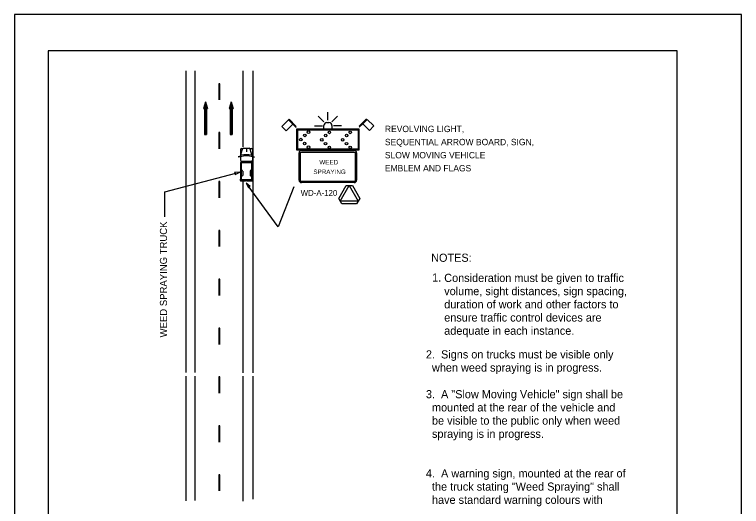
# Model space of a CAD drawing. Extents: x 1570 to 1794, y 169 to 448.
# Drawn here: x 1578.5 to 1794.5, y 301.9 to 448 of the extents above; entities that cross this region are included whole.
import ezdxf

# ---------------------------------------------------------------- set-up
doc = ezdxf.new("R2010")
doc.units = 0
for name, color, linetype in [('Level 1', 7, 'Continuous'), ('Level 10', 7, 'Continuous'), ('Level 2', 7, 'Continuous'), ('Level 44', 7, 'Continuous'), ('Level 60', 7, 'Continuous')]:
    doc.layers.add(name, color=color, linetype=linetype)

msp = doc.modelspace()

# ---------------------------------------------------------------- linework, layer by layer
at = {"layer": 'Level 1'}
for p, q in [((1646.51, 408.35), (1648.24, 408.35)), ((1647.37, 408.35), (1647.37, 407.24)), ((1645.6, 407.91), (1645.6, 404.82)), ((1645.66, 406.03), (1646.21, 408.09)), ((1645.9, 408.22), (1646.26, 408.22)), ((1648.49, 408.22), (1648.85, 408.22)), ((1649.07, 406.03), (1648.53, 408.09)), ((1649.14, 407.91), (1649.14, 404.82)), ((1645.6, 405.81), (1644.96, 405.74)), ((1645.6, 405.8), (1644.96, 405.72)), ((1645.6, 405.78), (1644.96, 405.7)), ((1645.6, 405.8), (1645.66, 406.03)), ((1645.6, 405.41), (1645.6, 405.41)), ((1645.6, 403.97), (1645.6, 399.15)), ((1645.82, 403.97), (1645.82, 399.15)), ((1645.9, 404.52), (1648.85, 404.52)), ((1645.9, 404.27), (1648.85, 404.27)), ((1645.9, 404.05), (1648.85, 404.05)), ((1648.92, 403.97), (1648.92, 399.15)), ((1649.14, 405.8), (1649.08, 406.03)), ((1649.14, 405.81), (1649.79, 405.74)), ((1649.14, 405.8), (1649.79, 405.72)), ((1649.14, 405.78), (1649.79, 405.7)), ((1649.14, 403.97), (1649.14, 399.15)), ((1645.82, 401.76), (1646.02, 401.76)), ((1648.92, 401.76), (1648.72, 401.76)), ((1645.82, 400.02), (1646.02, 400.02)), ((1646.26, 401.53), (1646.26, 400.25)), ((1648.49, 401.53), (1648.49, 400.25)), ((1648.92, 400.02), (1648.72, 400.02)), ((1645.54, 399.15), (1645.54, 398.89)), ((1645.83, 398.6), (1647.15, 398.6)), ((1645.9, 399.08), (1648.85, 399.08)), ((1645.9, 398.86), (1648.85, 398.86)), ((1647.6, 398.6), (1648.92, 398.6)), ((1649.21, 399.15), (1649.21, 398.89)), ((1674.8, 393.42), (1677, 397.23)), ((1675.26, 392.62), (1677.92, 397.23)), ((1677, 397.23), (1678.85, 397.23)), ((1677.92, 397.23), (1680.59, 392.62)), ((1678.85, 397.23), (1681.05, 393.42)), ((1675.72, 391.82), (1674.8, 393.42)), ((1681.05, 393.42), (1680.13, 391.82)), ((1680.59, 392.62), (1675.26, 392.62)), ((1680.13, 391.82), (1675.72, 391.82))]:
    msp.add_line(p, q, dxfattribs=at)
for centre, radius, start, end in [((1646.51, 408.05), 0.297, 90, 172.554), ((1648.24, 408.05), 0.297, 7.446, 90), ((1645.9, 407.92), 0.297, 90, 180), ((1645.95, 405.96), 0.297, 101.1133, 164.8989), ((1647.37, 398.73), 7.66, 78.8894, 101.1106), ((1648.85, 407.92), 0.297, 0, 90), ((1648.79, 405.96), 0.297, 14.8586, 78.8916), ((1647.37, 398.73), 7.29, 75.9432, 104.0544), ((1645.9, 404.82), 0.297, 180, 270), ((1645.9, 403.97), 0.297, 90, 180), ((1645.9, 403.97), 0.0766, 90, 180), ((1648.85, 404.82), 0.297, 270, 360), ((1648.85, 403.97), 0.297, 360, 90), ((1648.85, 403.97), 0.0766, 360, 90), ((1645.9, 399.15), 0.297, 180, 270), ((1645.9, 399.15), 0.0766, 180, 270), ((1648.85, 399.15), 0.297, 270, 360), ((1648.85, 399.15), 0.0766, 270, 360)]:
    msp.add_arc(centre, radius, start, end, dxfattribs=at)
at = {"layer": 'Level 10'}
for p, q in [((1786.24, 448.02), (1786.24, 448.02)), ((1629.33, 431.35), (1629.33, 341.73)), ((1632.06, 431.35), (1632.06, 341.68)), ((1646.28, 431.35), (1646.28, 408.73)), ((1649.3, 431.35), (1649.3, 341.62)), ((1635.19, 422.06), (1634.61, 420.13)), ((1634.97, 421.34), (1634.97, 412.39)), ((1635.05, 421.58), (1635.05, 412.39)), ((1635.12, 421.82), (1635.12, 412.39)), ((1635.19, 422.06), (1635.19, 412.39)), ((1635.19, 422.06), (1635.77, 420.13)), ((1635.26, 421.82), (1635.26, 412.39)), ((1635.34, 421.58), (1635.34, 412.39)), ((1635.41, 421.34), (1635.41, 412.39)), ((1642.84, 422.06), (1642.26, 420.13)), ((1642.62, 421.34), (1642.62, 412.39)), ((1642.7, 421.58), (1642.7, 412.39)), ((1642.77, 421.82), (1642.77, 412.39)), ((1642.84, 422.06), (1642.84, 412.39)), ((1642.84, 422.06), (1643.42, 420.13)), ((1642.91, 421.82), (1642.91, 412.39)), ((1642.99, 421.58), (1642.99, 412.39)), ((1643.06, 421.34), (1643.06, 412.39)), ((1634.61, 420.13), (1634.9, 420.13)), ((1634.68, 420.37), (1634.68, 420.13)), ((1634.76, 420.61), (1634.76, 420.13)), ((1634.83, 420.85), (1634.83, 420.13)), ((1634.9, 421.09), (1634.9, 412.39)), ((1634.9, 420.13), (1634.9, 412.39)), ((1635.48, 421.09), (1635.48, 412.39)), ((1635.48, 420.13), (1635.48, 412.39)), ((1635.48, 420.13), (1635.77, 420.13)), ((1635.55, 420.85), (1635.55, 420.13)), ((1635.63, 420.61), (1635.63, 420.13)), ((1635.7, 420.37), (1635.7, 420.13)), ((1642.26, 420.13), (1642.55, 420.13)), ((1642.33, 420.37), (1642.33, 420.13)), ((1642.41, 420.61), (1642.41, 420.13)), ((1642.48, 420.85), (1642.48, 420.13)), ((1642.55, 421.09), (1642.55, 412.39)), ((1642.55, 420.13), (1642.55, 412.39)), ((1643.13, 421.09), (1643.13, 412.39)), ((1643.13, 420.13), (1643.13, 412.39)), ((1643.13, 420.13), (1643.42, 420.13)), ((1643.2, 420.85), (1643.2, 420.13)), ((1643.28, 420.61), (1643.28, 420.13)), ((1643.35, 420.37), (1643.35, 420.13)), ((1660.03, 416.91), (1659.88, 416.75)), ((1670.42, 416.13), (1668.74, 417.81)), ((1671.58, 416.61), (1671.58, 418.99)), ((1672.74, 416.13), (1674.42, 417.81)), ((1681.93, 415.59), (1683.24, 416.9)), ((1683.24, 416.9), (1685.21, 414.93)), ((1659.88, 416.75), (1657.91, 414.78)), ((1657.91, 414.78), (1659.22, 413.47)), ((1659.22, 413.47), (1661.19, 415.44)), ((1661.19, 415.44), (1659.88, 416.75)), ((1661.19, 415.44), (1661.19, 415.44)), ((1667.56, 414.97), (1669.94, 414.97)), ((1670.37, 413.96), (1670.37, 415.05)), ((1671.3, 415.98), (1671.86, 415.98)), ((1671.56, 415.98), (1671.58, 415.98)), ((1672.79, 415.05), (1672.79, 413.96)), ((1675.6, 414.97), (1673.23, 414.97)), ((1683.9, 413.62), (1681.93, 415.59)), ((1681.93, 415.59), (1681.93, 415.59)), ((1685.21, 414.93), (1683.9, 413.62)), ((1672.79, 413.96), (1670.37, 413.96)), ((1634.9, 412.39), (1635.48, 412.39)), ((1642.55, 412.39), (1643.13, 412.39)), ((1663.02, 398.8), (1663.02, 406.97)), ((1663.71, 407.67), (1679.42, 407.67)), ((1671.57, 407.67), (1671.57, 407.67)), ((1680.12, 406.97), (1680.12, 398.8)), ((1645.54, 399.15), (1645.6, 399.15)), ((1646.28, 398.6), (1646.28, 341.62)), ((1649.21, 399.15), (1649.14, 399.15)), ((1679.42, 398.1), (1663.71, 398.1)), ((1629.33, 340.65), (1629.33, 303.63)), ((1632.06, 340.65), (1632.06, 303.75)), ((1646.28, 340.65), (1646.28, 303.5)), ((1649.3, 340.65), (1649.3, 304.12))]:
    msp.add_line(p, q, dxfattribs=at)
msp.add_lwpolyline([(1663.45, 407.2), (1679.67, 407.2), (1679.67, 398.46), (1663.45, 398.46)], close=True, dxfattribs=at)
for points in [[(1623.17, 387.99), (1623.17, 395.39), (1644.23, 400.91)], [(1661.42, 396.82), (1656.81, 385), (1647.89, 397.12)]]:
    msp.add_lwpolyline(points, dxfattribs=at)
msp.add_circle((1647.37, 398.64), 0.0581, dxfattribs=at)
for centre, radius, start, end in [((1671.3, 415.05), 0.929, 90, 180), ((1671.86, 415.05), 0.929, 0, 90), ((1663.71, 406.97), 0.697, 90, 180), ((1679.42, 406.97), 0.697, 0, 90), ((1646.02, 401.53), 0.232, 0, 90), ((1648.72, 401.53), 0.232, 90, 180), ((1646.02, 400.25), 0.232, 270, 0), ((1648.72, 400.25), 0.232, 180, 270), ((1645.83, 398.89), 0.29, 180, 270), ((1647.37, 398.64), 0.174, 29.9957, 149.9771), ((1648.92, 398.89), 0.29, 270, 0), ((1663.71, 398.8), 0.697, 180, 270), ((1679.42, 398.8), 0.697, 270, 0)]:
    msp.add_arc(centre, radius, start, end, dxfattribs=at)
at = {"layer": 'Level 2'}
for p, q in [((1639.15, 427.49), (1639.15, 422.65)), ((1639.44, 427.49), (1639.15, 427.49)), ((1639.44, 422.65), (1639.44, 427.49)), ((1639.15, 412.97), (1639.15, 408.13)), ((1639.44, 412.97), (1639.15, 412.97)), ((1639.44, 408.13), (1639.44, 412.97)), ((1639.15, 398.46), (1639.15, 393.62)), ((1639.44, 398.46), (1639.15, 398.46)), ((1639.44, 393.62), (1639.44, 398.46)), ((1639.15, 383.94), (1639.15, 379.11)), ((1639.44, 383.94), (1639.15, 383.94)), ((1639.44, 379.11), (1639.44, 383.94)), ((1639.15, 369.43), (1639.15, 364.59)), ((1639.44, 369.43), (1639.15, 369.43)), ((1639.44, 364.59), (1639.44, 369.43)), ((1639.15, 354.92), (1639.15, 350.08)), ((1639.44, 354.92), (1639.15, 354.92)), ((1639.44, 350.08), (1639.44, 354.92)), ((1639.15, 340.4), (1639.15, 335.56)), ((1639.44, 340.4), (1639.15, 340.4)), ((1639.44, 335.56), (1639.44, 340.4)), ((1639.15, 325.89), (1639.15, 321.05)), ((1639.44, 325.89), (1639.15, 325.89)), ((1639.44, 321.05), (1639.44, 325.89)), ((1639.15, 311.37), (1639.15, 306.54)), ((1639.44, 311.37), (1639.15, 311.37)), ((1639.44, 306.54), (1639.44, 311.37))]:
    msp.add_line(p, q, dxfattribs=at)
at = {"layer": 'Level 44'}
for p, q in [((1662.2, 414.74), (1660.03, 416.91)), ((1680.92, 414.89), (1683.09, 417.06)), ((1662.2, 414.43), (1661.19, 415.44)), ((1680.92, 414.58), (1681.93, 415.59)), ((1680.92, 413.96), (1662.25, 413.96)), ((1662.25, 413.96), (1662.25, 407.83)), ((1662.52, 413.68), (1662.52, 408.1)), ((1680.64, 413.68), (1662.53, 413.68)), ((1662.53, 413.68), (1662.53, 408.1)), ((1680.64, 408.1), (1680.64, 413.68)), ((1680.92, 407.83), (1680.92, 413.96)), ((1662.25, 407.83), (1680.92, 407.83)), ((1662.53, 408.1), (1680.64, 408.1))]:
    msp.add_line(p, q, dxfattribs=at)
for centre in [(1665.8, 413.08), (1672.02, 413.03), (1678.23, 413.03), (1663.54, 410.89), (1664.72, 412.14), (1669.75, 410.84), (1670.93, 412.1), (1675.97, 410.84), (1677.15, 412.1), (1664.67, 409.71), (1665.8, 408.62), (1670.89, 409.67), (1672.02, 408.58), (1677.1, 409.67), (1678.23, 408.58)]:
    msp.add_circle(centre, 0.383, dxfattribs=at)
at = {"layer": 'Level 60'}
msp.add_line((1794.47, 448.02), (1794.47, 448.02), dxfattribs=at)
for points in [[(1794.47, 448.02), (1578.47, 448.02), (1578.47, 169.02), (1794.47, 169.02)], [(1775.35, 437.21), (1588.47, 437.21), (1588.47, 179.83), (1775.35, 179.83)], [(1644, 400.53), (1645.37, 401.2), (1643.85, 401.11), (1644.02, 400.84)], [(1648.47, 396.92), (1647.34, 397.95), (1647.98, 396.57), (1648.17, 396.83)]]:
    msp.add_lwpolyline(points, close=True, dxfattribs=at)

# ---------------------------------------------------------------- texts
at = {"layer": 'Level 10'}
for s, height, p in [('REVOLVING LIGHT,', 1.887, (1688.52, 413.11)), ('SEQUENTIAL ARROW BOARD, SIGN,', 1.887, (1688.52, 409.22)), ('SLOW MOVING VEHICLE', 1.887, (1688.52, 405.33)), ('WEED', 1.35, (1669.04, 403.5)), ('SPRAYING', 1.35, (1667.26, 400.65)), ('EMBLEM AND FLAGS', 1.887, (1688.52, 401.45)), ('NOTES:', 2.419, (1702.26, 374.6)), ('1.', 2.419, (1702.55, 368.72)), ('Consideration must be given to traffic ', 2.419, (1706.15, 368.61)), ('volume, sight distances, sign spacing, ', 2.419, (1706.15, 364.69)), ('duration of work and other factors to ', 2.419, (1706.15, 360.77)), ('ensure traffic control devices are ', 2.419, (1706.15, 356.85)), ('adequate in each instance.', 2.419, (1706.15, 352.93)), ('2.  Signs on trucks must be visible only ', 2.419, (1700.71, 345.9)), ('  when weed spraying is in progress.', 2.419, (1700.71, 341.98)), ('3.  A "Slow Moving Vehicle" sign shall be', 2.419, (1700.71, 334.08)), ('  mounted at the rear of the vehicle and', 2.419, (1700.71, 330.16)), ('  be visible to the public only when weed', 2.419, (1700.71, 326.24)), ('  spraying is in progress.', 2.419, (1700.71, 322.32)), ('4.  A warning sign, mounted at the rear of ', 2.419, (1700.71, 310.56)), ('  the truck stating "Weed Spraying" shall ', 2.419, (1700.71, 306.64)), ('  have standard warning colours with', 2.419, (1700.71, 302.72))]:
    msp.add_text(s, height=height, dxfattribs=at).set_placement(p)
for s, height, rotation, p in [('WD-A-120', 1.742, 360, (1663.5, 394.18)), ('WEED SPRAYING TRUCK', 2.115, 90, (1623.78, 352.15))]:
    msp.add_text(s, height=height, rotation=rotation, dxfattribs=at).set_placement(p)

doc.saveas('drawing.dxf')
